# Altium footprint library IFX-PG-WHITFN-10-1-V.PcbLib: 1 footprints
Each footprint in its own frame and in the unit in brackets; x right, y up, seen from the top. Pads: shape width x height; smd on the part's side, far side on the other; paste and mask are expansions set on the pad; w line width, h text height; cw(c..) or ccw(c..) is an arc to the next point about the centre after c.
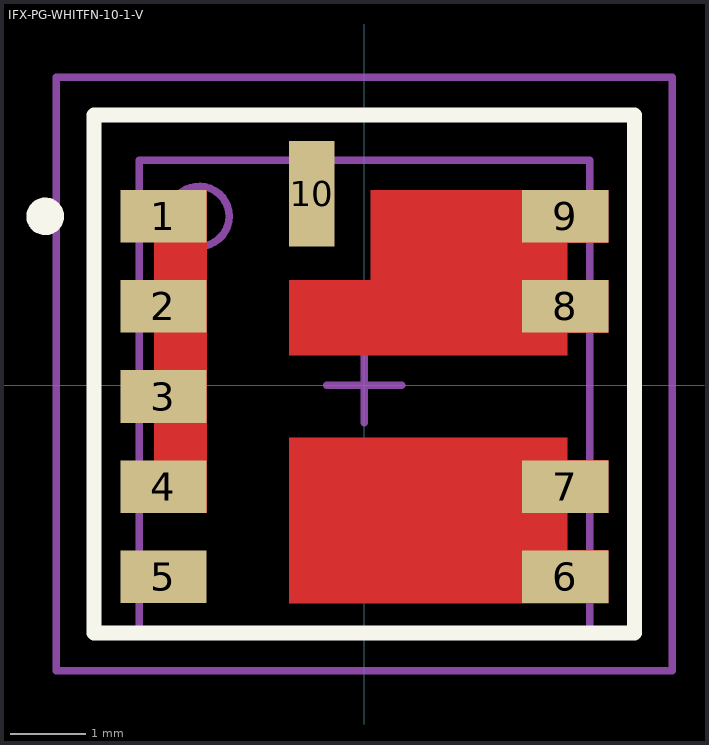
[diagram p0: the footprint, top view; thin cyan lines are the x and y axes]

## IFX-PG-WHITFN-10-1-V [mm] "WHITFN-10-1, SMD, 1.20 mm pitch, 10 pin, 6.0 mm L X 6.30 mm W X 0.80 mm H body"
height 0.8
pads (10):
  rect 1.15x0.7 smd paste-0.575 mask+0: 1(-2.675,2.25) 2(-2.675,1.05) 3(-2.675,-0.15) 4(-2.675,-1.35) 5(-2.675,-2.55) 6(2.675,-2.55) 7(2.675,-1.35) 8(2.675,1.05) 9(2.675,2.25)
  rect 0.6x1.4 smd paste-0.06 mask+0: 10(-0.7,2.55)
Top Layer:
  region: 3.25,2.6 3.25,1.9 2.705,1.9 2.705,1.4 3.25,1.4 3.25,0.7 2.705,0.7 2.705,0.4 -1,0.4 -1,1.4 0.085,1.4 0.085,2.6
  region: 2.705,-0.7 2.705,-1 3.25,-1 3.25,-1.7 2.705,-1.7 2.705,-2.2 3.25,-2.2 3.25,-2.9 -1,-2.9 -1,-0.7
  region: -2.8,2.6 -2.1,2.6 -2.1,-1.7 -2.8,-1.7
Top Overlay:
  circle w0.25: c-4.25,2.25 r0.125
  lines w0.2: -3.6,-3.3 -3.6,3.6 3.6,3.6 3.6,-3.3 -3.6,-3.3
Top Paste:
  region: -3.23,-1.02 -2.85,-1.02 -2.85,-1.68 -3.23,-1.68
  region: -3.23,0.18 -2.85,0.18 -2.85,-0.48 -3.23,-0.48
  region: -3.23,1.38 -2.85,1.38 -2.85,0.72 -3.23,0.72
  region: -3.23,2.58 -2.85,2.58 -2.85,1.92 -3.23,1.92
  region: -3.175,-2.27 -2.175,-2.27 -2.175,-2.83 -3.175,-2.83
  region: -2.65,2.58 -2.12,2.58 -2.12,0.55 -2.65,0.55
  region: -2.65,0.35 -2.12,0.35 -2.12,-1.68 -2.65,-1.68
  region: -0.977,1.383 -0.012,1.383 -0.012,0.437 -0.977,0.437
  region: 1.535,2.568 2.685,2.568 2.685,1.602 1.535,1.602
  region: 0.185,2.568 1.335,2.568 1.335,1.602 0.185,1.602
  region: 1.535,1.403 2.685,1.403 2.685,0.437 1.535,0.437
  region: 0.185,1.403 1.335,1.403 1.335,0.437 0.185,0.437
  region: 1.605,-1.887 2.685,-1.887 2.685,-2.853 1.605,-2.853
  region: 0.325,-1.887 1.405,-1.887 1.405,-2.853 0.325,-2.853
  region: -0.955,-1.887 0.125,-1.887 0.125,-2.853 -0.955,-2.853
  region: -0.955,-0.723 0.125,-0.723 0.125,-1.688 -0.955,-1.688
  region: 0.325,-0.723 1.405,-0.723 1.405,-1.688 0.325,-1.688
  region: 1.605,-0.723 2.685,-0.723 2.685,-1.688 1.605,-1.688
  region: 2.888,2.58 3.233,2.58 3.233,1.92 2.888,1.92
  region: 2.888,1.38 3.233,1.38 3.233,0.72 2.888,0.72
  region: 2.888,-1.02 3.233,-1.02 3.233,-1.68 2.888,-1.68
  region: 2.888,-2.22 3.233,-2.22 3.233,-2.88 2.888,-2.88
M3 (ASY_Text_Top):
  text ".DESIGNATOR" at -3.643,-0.385 h1.2
M13 (CMP_Body_OTL_Top):
  circle w0.1: c-2.2,2.25 r0.4
  lines w0.1: -3,-3.3 -3,3 3,3 3,-3.3 -3,-3.3
M15 (CMP_Courtyard_Top):
  lines w0.1: -0.5,0 0.5,0 ; 0,-0.5 0,0.5 ; -4.1,-3.8 -4.1,4.1 4.1,4.1 4.1,-3.8 -4.1,-3.8
3D body "PG-WHITFN-10-1_Z8B00204926_V01_3D.stp": height 0.8, standoff 0, extent -3,-3.3 3,3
